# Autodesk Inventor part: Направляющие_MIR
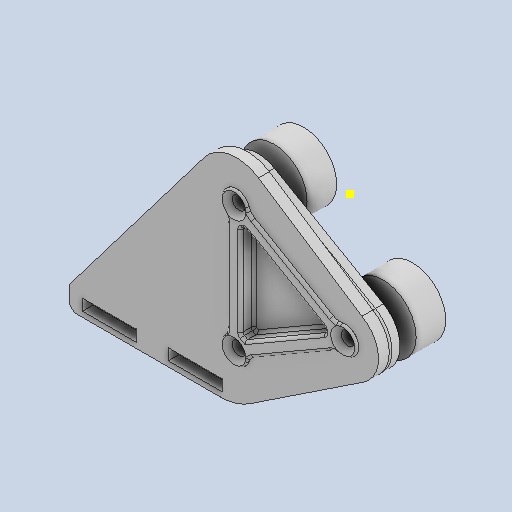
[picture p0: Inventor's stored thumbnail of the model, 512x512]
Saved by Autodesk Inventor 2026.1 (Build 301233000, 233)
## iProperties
Created: 2025-12
Part Number: Направляющие_MIR
Material: Типовые
Document SubType Name: Modeling
Designer: Yury Melnikov
Density: 1 g/cm^3
Appearance: По умолчанию
Author: Yury Melnikov
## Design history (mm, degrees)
derived "Направляющие.ipt"
  sketch "Эскиз1"
    geometry: L1 (0, 0)-(-16, 0) reference; L2 (-16, 0)-(-16, -200) reference; L3 (-16, -200)-(0, -200) reference; L4 (0, -200)-(0, 0) reference; 1 further point
  sketch "Эскиз2"
    geometry: 1 further point
  sketch "Эскиз3"
    geometry: L1 (0, 0)-(0, -200) reference; L2 (16, -200)-(16, 0) reference; L3 (28.3, -33.725)-(-12.3, -10.284) reference; L4 (-12.3, -10.284)-(-12.3, -57.165) reference; L5 (-12.3, -57.165)-(28.3, -33.725) reference; C1 r 12.3 at (28.3, -33.725) reference; C2 r 12.3 at (-12.3, -10.284) reference; C3 r 12.3 at (-12.3, -57.165) reference; 1 further point
    constraints: 1 other
  sketch "Эскиз4"
    geometry: C1 r 12.3 at (0, 0) reference; C2 r 12.3 at (-40.6, 23.44) reference; C3 r 12.3 at (-40.6, -23.44) reference; C4 r 4 at (0, 0) reference; C5 r 4 at (-40.6, 23.44) reference; C6 r 4 at (-40.6, -23.44) reference; 1 further point
  sketch "Эскиз5"
    geometry: L1 (6.15, 10.652)-(-34.45, 34.093) reference; L2 (-52.9, 23.44)-(-52.9, -23.44) reference; L3 (-34.45, -34.093)-(6.15, -10.652) reference; A1 r 12.3 centre (-40.6, -23.44) between (-34.45, -34.093) and (-52.9, -23.44) reference; A2 r 12.3 centre (-40.6, 23.44) between (-52.9, 23.44) and (-34.45, 34.093) reference; A3 r 12.3 centre (0, 0) between (6.15, -10.652) and (6.15, 10.652) reference; 1 further point
  sketch "Эскиз6"
    geometry: L1 (0, 0)-(-40.6, 23.44) reference; L2 (-40.6, 23.44)-(-40.6, -23.44) reference; L3 (-40.6, -23.44)-(0, 0) reference; L4 (-35.6, 23.44)-(-2.5, 4.33) reference; L5 (-2.5, -4.33)-(-35.6, -23.44) reference; L6 (-43.1, -19.11)-(-43.1, 19.11) reference; L7 (-38.1, 19.11)-(-5, 0) reference; L8 (-5, 0)-(-38.1, -19.11) reference; L9 (-38.1, -19.11)-(-38.1, 19.11) reference; C1 r 12.3 at (-40.6, 23.44) reference; C2 r 12.3 at (-40.6, -23.44) reference; C3 r 12.3 at (0, 0) reference; C4 r 2.5 at (0, 0) reference; C5 r 2.5 at (-40.6, 23.44) reference; C6 r 2.5 at (-40.6, -23.44) reference; A1 r 5 centre (-40.6, 23.44) between (-35.6, 23.44) and (-43.1, 19.11) reference; A2 r 5 centre (0, 0) between (-2.5, -4.33) and (-2.5, 4.33) reference; A3 r 5 centre (-40.6, -23.44) between (-43.1, -19.11) and (-35.6, -23.44) reference; 3 further points
    constraints: 2 other
  sketch "Эскиз7"
    geometry: C1 r 2.5 at (-40.6, 23.44) reference; C2 r 2.5 at (0, 0) reference; C3 r 2.5 at (-40.6, -23.44) reference; 1 further point
  sketch "Эскиз8"
    geometry: L1 (-4.478, 5.472)-(-33.622, 22.298) reference; L2 (-43.1, 16.826)-(-43.1, -16.826) reference; L3 (-33.622, -22.298)-(-4.478, -5.472) reference; L4 (-34.45, 34.093)-(6.15, 10.652) reference; L5 (6.15, -10.652)-(-34.45, -34.093) reference; L6 (-52.9, -23.44)-(-52.9, 23.44) reference; L7 (-30, -82.992)-(-34, -82.992) reference; L8 (-28.3, 33.725)-(-28.3, -166.275) reference; L9 (-102.9, -34.753)-(-102.9, -38.74) reference; L10 (-99.9, -41.74)-(-46.638, -41.74) reference; L11 (-35.571, -38.399)-(6.806, -10.245) reference; L12 (-34.45, 34.093)-(6.15, 10.652) reference; L13 (6.15, 10.652)-(-32.359, 35.974) reference; L14 (-102.288, -32.938)-(-52.542, 32.517) reference; A1 r 5 centre (-1.978, -9.802) between (-0.989, -4.901) and (-4.478, -5.472) reference; A2 r 5 centre (0, 0) between (-0.989, -4.901) and (-0.989, 4.901) reference; A3 r 5 centre (-1.978, 9.802) between (-4.478, 5.472) and (-0.989, 4.901) reference; A4 r 5 centre (-31.122, 26.628) between (-35.861, 25.034) and (-33.622, 22.298) reference; A5 r 5 centre (-40.6, 23.44) between (-35.861, 25.034) and (-44.35, 20.133) reference; A6 r 5 centre (-48.1, 16.826) between (-43.1, 16.826) and (-44.35, 20.133) reference; A7 r 5 centre (-48.1, -16.826) between (-44.35, -20.133) and (-43.1, -16.826) reference; A8 r 5 centre (-40.6, -23.44) between (-44.35, -20.133) and (-35.861, -25.034) reference; A9 r 5 centre (-31.122, -26.628) between (-33.622, -22.298) and (-35.861, -25.034) reference; A10 r 12.3 centre (-40.6, 23.44) between (-34.45, 34.093) and (-52.9, 23.44) reference; A11 r 12.3 centre (0, 0) between (6.15, -10.652) and (6.15, 10.652) reference; A12 r 12.3 centre (-40.6, -23.44) between (-52.9, -23.44) and (-34.45, -34.093) reference; A13 r 12.3 centre (0, 0) between (6.15, -10.652) and (6.15, 10.652) reference; A14 r 12.3 centre (-40.6, 23.44) between (-34.45, 34.093) and (-52.9, 23.44) reference; A15 r 20 centre (-46.638, -21.74) between (-46.638, -41.74) and (-35.571, -38.399) reference; A16 r 3 centre (-99.9, -34.753) between (-102.288, -32.938) and (-102.9, -34.753) reference; A17 r 3 centre (-99.9, -38.74) between (-102.9, -38.74) and (-99.9, -41.74) reference; A18 r 15 centre (-40.6, 23.44) between (-28.3, 14.855) and (-26.541, 18.21) reference; A19 r 15 centre (-40.6, 23.44) between (-32.359, 35.974) and (-52.542, 32.517) reference; 5 further points
  node "РабПлоскость1"
feature "Твердое тело1::Направляющие.ipt" dims "d0" = 10
feature "Твердое тело2::Направляющие.ipt" dims "d0" = 10
feature "Твердое тело3::Направляющие.ipt" dims "d0" = 10
feature "Твердое тело4::Направляющие.ipt" dims "d0" = 10
tag "Элемент создания тегов1"
sketch "Эскиз11"
  geometry: L1 (6.806, -10.245)-(-35.571, -38.399) reference; L2 (-46.638, -41.74)-(-99.9, -41.74) reference; L3 (-102.9, -38.74)-(-102.9, -34.753) reference; L4 (-33.622, -22.298)-(-4.478, -5.472) reference; L5 (-4.478, 5.472)-(-33.622, 22.298) reference; L6 (-43.1, 16.826)-(-43.1, -16.826) reference; L7 (-31.268, -35.54)-(-102.9, -35.54) reference; L8 (-37.92, -39.74)-(-102.728, -39.74) reference; L9 (-45.92, -35.54)-(-65.92, -35.54) reference; L10 (-65.92, -35.54)-(-65.92, -39.74) reference; L11 (-65.92, -39.74)-(-45.92, -39.74) reference; L12 (-45.92, -39.74)-(-45.92, -35.54) reference; L13 (-77.9, -35.54)-(-97.9, -35.54) reference; L14 (-97.9, -35.54)-(-97.9, -39.74) reference; L15 (-97.9, -39.74)-(-77.9, -39.74) reference; L16 (-77.9, -39.74)-(-77.9, -35.54) reference; L17 (-32.359, 35.974)-(6.15, 10.652) reference; L18 (-102.288, -32.938)-(-52.542, 32.517) reference; A1 r 12.3 centre (0, 0) between (6.806, -10.245) and (6.15, 10.652) reference; A2 r 20 centre (-46.638, -21.74) between (-46.638, -41.74) and (-35.571, -38.399) reference; A3 r 3 centre (-99.9, -38.74) between (-102.9, -38.74) and (-99.9, -41.74) reference; A4 r 3 centre (-99.9, -34.753) between (-102.288, -32.938) and (-102.9, -34.753) reference; A5 r 5 centre (-1.978, -9.802) between (-0.989, -4.901) and (-4.478, -5.472) reference; A6 r 5 centre (0, 0) between (-0.989, -4.901) and (-0.989, 4.901) reference; A7 r 5 centre (-1.978, 9.802) between (-4.478, 5.472) and (-0.989, 4.901) reference; A8 r 5 centre (-31.122, 26.628) between (-35.861, 25.034) and (-33.622, 22.298) reference; A9 r 5 centre (-40.6, 23.44) between (-35.861, 25.034) and (-44.35, 20.133) reference; A10 r 5 centre (-48.1, 16.826) between (-43.1, 16.826) and (-44.35, 20.133) reference; A11 r 5 centre (-48.1, -16.826) between (-44.35, -20.133) and (-43.1, -16.826) reference; A12 r 5 centre (-40.6, -23.44) between (-44.35, -20.133) and (-35.861, -25.034) reference; A13 r 5 centre (-31.122, -26.628) between (-33.622, -22.298) and (-35.861, -25.034) reference; A14 r 15 centre (-40.6, 23.44) between (-32.359, 35.974) and (-52.542, 32.517) reference; 1 further point
node "Твердое тело1"
node "Твердое тело2"
node "Твердое тело3"
node "Твердое тело4"
